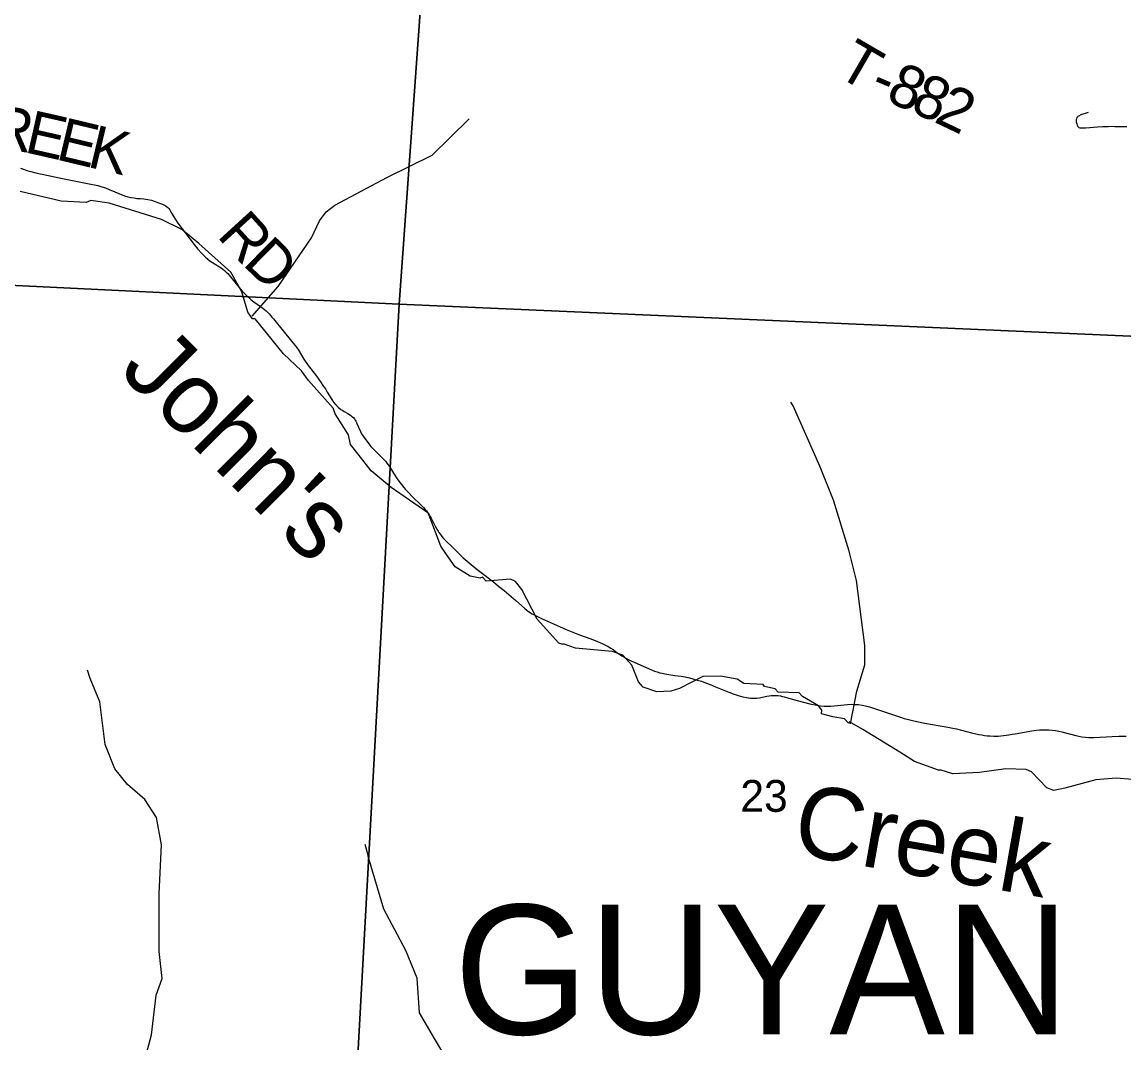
# Model space of a CAD drawing. Extents: x 396.2 to 468.4, y 232.6 to 279.1.
# Drawn here: x 416.745 to 418.195, y 268.432 to 269.775 of the extents above; entities that cross this region are included whole.
import ezdxf

# ---------------------------------------------------------------- set-up
doc = ezdxf.new("R2010")
doc.units = 0
for name, color, linetype in [('GM_X_County_Road', 7, 'Continuous'), ('GM_X_County_Road_Text', 7, 'Continuous'), ('GM_X_Minor_River', 7, 'Continuous'), ('GM_X_Minor_River_Text', 7, 'Continuous'), ('GM_X_Section', 7, 'Continuous'), ('GM_X_Section_Text', 7, 'Continuous'), ('GM_X_Township_Road', 7, 'Continuous'), ('GM_X_Township_Road_Text', 7, 'Continuous'), ('GM_X_Township_Text', 7, 'Continuous')]:
    doc.layers.add(name, color=color, linetype=linetype)

msp = doc.modelspace()

# ---------------------------------------------------------------- linework, layer by layer
at = {"layer": 'GM_X_County_Road'}
for points in [[(416.7431, 269.5829), (416.7469, 269.5815), (416.7512, 269.5799), (416.7568, 269.5783), (416.7633, 269.5767), (416.7981, 269.5693), (416.8356, 269.562), (416.8404, 269.561), (416.845, 269.56), (416.8502, 269.5585), (416.8549, 269.5569), (416.8596, 269.555), (416.8798, 269.5467), (416.8844, 269.5452), (416.8883, 269.5443), (416.8924, 269.5437), (416.8963, 269.5432), (416.9009, 269.5428), (416.9055, 269.5424), (416.9105, 269.5417), (416.9156, 269.5406), (416.9204, 269.5392), (416.9248, 269.5375), (416.9297, 269.5354), (416.9332, 269.5337), (416.935, 269.5326), (416.9367, 269.5313), (416.9382, 269.5297), (416.9395, 269.528), (416.9406, 269.5262), (416.9419, 269.5239), (416.95, 269.5107), (416.9714, 269.4824), (416.9763, 269.4765), (416.9811, 269.4711), (416.9865, 269.4659), (416.9924, 269.461), (416.999, 269.4566), (417.0049, 269.453), (417.0071, 269.4517), (417.0095, 269.4499), (417.0117, 269.4481), (417.0139, 269.4461), (417.016, 269.4441), (417.0178, 269.442), (417.0307, 269.4259), (417.0325, 269.4236), (417.0346, 269.4212), (417.0369, 269.4188), (417.0408, 269.4151), (417.0461, 269.4103), (417.0501, 269.4069), (417.0618, 269.3985), (417.0641, 269.397), (417.0664, 269.3952), (417.0684, 269.3932), (417.0702, 269.3913), (417.0723, 269.3888), (417.0739, 269.3869), (417.0759, 269.3845), (417.0887, 269.3688), (417.0997, 269.3554), (417.1061, 269.3474), (417.1072, 269.3459), (417.1084, 269.3442), (417.116, 269.3315), (417.1218, 269.3233), (417.1316, 269.3105), (417.1378, 269.302), (417.142, 269.2958), (417.1443, 269.2924), (417.1468, 269.2884), (417.1527, 269.2784), (417.1551, 269.2749), (417.1579, 269.2716), (417.1609, 269.2686), (417.1648, 269.2656), (417.1673, 269.264)], [(417.1673, 269.264), (417.169, 269.2629), (417.1738, 269.2602), (417.1773, 269.2579), (417.1787, 269.2568), (417.18, 269.2557), (417.1815, 269.2543), (417.1826, 269.2529), (417.1836, 269.2514), (417.1844, 269.2499), (417.1851, 269.2484), (417.1857, 269.2468), (417.1903, 269.2363), (417.192, 269.2335), (417.1939, 269.2303), (417.2016, 269.22), (417.2042, 269.2169), (417.2074, 269.2133), (417.2144, 269.2063), (417.2165, 269.2043), (417.2183, 269.2025), (417.2203, 269.2005), (417.2222, 269.1986), (417.2237, 269.1968), (417.2253, 269.1948), (417.2269, 269.1927), (417.2285, 269.1905), (417.2341, 269.1817), (417.2398, 269.173), (417.2477, 269.1628), (417.2498, 269.1603), (417.2525, 269.1573), (417.2592, 269.1502), (417.2695, 269.1406), (417.2717, 269.1384), (417.2735, 269.1364), (417.2755, 269.134), (417.2772, 269.1321), (417.2786, 269.13), (417.2799, 269.1281), (417.2811, 269.1264), (417.2822, 269.1246), (417.2833, 269.1225), (417.2844, 269.1206), (417.2888, 269.1119), (417.2909, 269.1081), (417.2925, 269.1054), (417.2937, 269.1036), (417.2956, 269.1009), (417.2976, 269.0984), (417.2998, 269.0958), (417.3034, 269.0922), (417.3116, 269.0843), (417.3258, 269.0704), (417.344, 269.055), (417.3565, 269.0457), (417.3609, 269.0423), (417.3656, 269.0386), (417.3723, 269.0331), (417.3794, 269.0271), (417.395, 269.014), (417.4061, 269.0039), (417.4098, 269.0008), (417.413, 268.9986), (417.4164, 268.9965), (417.4206, 268.9942), (417.4289, 268.9904), (417.4443, 268.9835), (417.4612, 268.9761), (417.4785, 268.969), (417.4921, 268.9639), (417.4993, 268.9613), (417.5054, 268.9589), (417.5092, 268.9573), (417.5127, 268.9555), (417.5164, 268.9535), (417.5198, 268.9515), (417.5229, 268.9495), (417.5259, 268.9472), (417.5304, 268.9439), (417.5345, 268.9411), (417.5383, 268.939), (417.5427, 268.9366), (417.5516, 268.9324), (417.5735, 268.9229), (417.5774, 268.9213), (417.5811, 268.9201), (417.5843, 268.9191), (417.5875, 268.9183), (417.5911, 268.9176), (417.6042, 268.9156), (417.6086, 268.9151), (417.6124, 268.9144), (417.6177, 268.9135), (417.6235, 268.9123), (417.6336, 268.9093), (417.6391, 268.9078), (417.6447, 268.906), (417.6507, 268.9036), (417.6579, 268.9006), (417.6687, 268.896), (417.6751, 268.8933), (417.6808, 268.8912), (417.6873, 268.8891), (417.6936, 268.8873), (417.6986, 268.8863), (417.7036, 268.8857), (417.7082, 268.8854), (417.7123, 268.8856), (417.7158, 268.8861), (417.723, 268.8877), (417.7254, 268.8882), (417.7282, 268.8887), (417.7311, 268.889), (417.7339, 268.8891), (417.7368, 268.8891), (417.74, 268.889), (417.7432, 268.8886), (417.746, 268.888), (417.7482, 268.8874), (417.7653, 268.8825), (417.7819, 268.8782), (417.791, 268.8764), (417.7958, 268.8756), (417.8005, 268.8751), (417.8053, 268.8749), (417.8094, 268.875), (417.8316, 268.8774), (417.8361, 268.8775), (417.841, 268.8774), (417.8458, 268.8771), (417.8505, 268.8764), (417.8553, 268.8754), (417.8603, 268.874), (417.8657, 268.8723), (417.9012, 268.8605), (417.906, 268.859), (417.9117, 268.8574), (417.9171, 268.8561), (417.9226, 268.8549), (417.9332, 268.8528), (417.9636, 268.8474), (417.97, 268.8463), (417.9747, 268.8452), (417.9945, 268.8401), (418.0043, 268.8379), (418.0082, 268.8372), (418.0117, 268.8367), (418.0151, 268.8362), (418.019, 268.8359), (418.024, 268.8356), (418.0297, 268.8358), (418.0333, 268.8361), (418.0367, 268.8364), (418.0402, 268.8368), (418.0439, 268.8374), (418.048, 268.8381), (418.0519, 268.8388), (418.0739, 268.8427), (418.0795, 268.8435), (418.084, 268.8439), (418.0884, 268.844), (418.0927, 268.844), (418.0962, 268.8439), (418.1007, 268.8436), (418.1051, 268.843), (418.1094, 268.8423), (418.1134, 268.8415), (418.132, 268.8366), (418.136, 268.8357), (418.1399, 268.8349), (418.1446, 268.8343), (418.1489, 268.8339), (418.152, 268.8337), (418.1557, 268.8338), (418.1796, 268.8352), (418.1885, 268.8354), (418.1932, 268.8355), (418.198, 268.8354)]]:
    msp.add_lwpolyline(points, dxfattribs=at)
at = {"layer": 'GM_X_Minor_River'}
for points in [[(417.0478, 269.388), (417.082, 269.4272), (417.126, 269.4912), (417.1365, 269.5136), (417.1451, 269.5255), (417.1565, 269.5342), (417.2261, 269.5711), (417.2847, 269.5999), (417.3334, 269.648)], [(417.0891, 269.3388), (417.052, 269.3847), (417.0483, 269.3847), (417.0422, 269.3934), (417.0342, 269.42), (417.0214, 269.4428), (417.0199, 269.4462), (416.9775, 269.4837), (416.9555, 269.5023), (416.9287, 269.5155), (416.8599, 269.537), (416.8357, 269.5404), (416.8293, 269.5377), (416.7964, 269.5395), (416.7427, 269.552)], [(418.2063, 268.7788), (418.1851, 268.7803), (418.1583, 268.7783), (418.1175, 268.7672), (418.1031, 268.7641), (418.0937, 268.7675), (418.0736, 268.7887), (418.0664, 268.7918), (418.0396, 268.7928), (418.0052, 268.7878), (417.97, 268.7862), (417.9549, 268.7911), (417.9511, 268.7911), (417.9194, 268.8024), (417.9005, 268.8145), (417.8517, 268.8444), (417.8339, 268.8546), (417.8328, 268.8527), (417.8275, 268.8584), (417.812, 268.861), (417.7972, 268.8652), (417.7976, 268.8698), (417.7934, 268.8754), (417.7722, 268.8879), (417.7677, 268.8925), (417.7401, 268.8935), (417.7363, 268.8981), (417.7223, 268.9011), (417.7204, 268.9034), (417.6951, 268.9048), (417.6864, 268.9105), (417.6641, 268.9146), (417.6411, 268.9142), (417.6101, 268.8985), (417.5987, 268.8947), (417.5806, 268.8939), (417.5624, 268.8999), (417.5564, 268.9071), (417.5477, 268.9291), (417.5359, 268.942), (417.5219, 268.9469), (417.4736, 268.9514), (417.4584, 268.9567), (417.4554, 268.9567), (417.4513, 268.9578), (417.4232, 268.9896), (417.4028, 269.0287), (417.3945, 269.039), (417.388, 269.042), (417.3559, 269.0396), (417.351, 269.0446), (417.348, 269.0434), (417.3347, 269.046), (417.3151, 269.0585), (417.3037, 269.0745), (417.2961, 269.0855), (417.281, 269.1261), (417.2791, 269.1295), (417.2307, 269.1628), (417.2046, 269.1848), (417.1875, 269.2068), (417.1773, 269.2193), (417.1747, 269.2319), (417.1573, 269.2596), (417.1546, 269.2672), (417.1221, 269.3036), (417.113, 269.3161), (417.0891, 269.3388)], [(417.8355, 268.8517), (417.8436, 268.8948), (417.8541, 268.9294), (417.8541, 268.9548), (417.8431, 269.0406), (417.8337, 269.0789), (417.813, 269.146), (417.7951, 269.191), (417.7597, 269.2703), (417.7568, 269.2749)], [(416.9266, 268.2329), (416.9114, 268.2697), (416.912, 268.313), (416.9195, 268.3495), (416.9187, 268.3731), (416.9079, 268.4016), (416.907, 268.4115), (416.9152, 268.4427), (416.9217, 268.4949), (416.9295, 268.5167), (416.9257, 268.5521), (416.9253, 268.6281), (416.9284, 268.6925), (416.9219, 268.7284), (416.9068, 268.7521), (416.884, 268.7722), (416.8672, 268.7928), (416.8563, 268.8201), (416.8546, 268.8247), (416.8476, 268.8808), (416.8345, 268.9116), (416.8314, 268.9223)], [(417.3363, 268.1294), (417.3359, 268.145), (417.3408, 268.1946), (417.3354, 268.227), (417.3132, 268.3063), (417.3124, 268.3177), (417.317, 268.3328), (417.321, 268.3501), (417.3143, 268.3936), (417.2877, 268.4377), (417.268, 268.4718), (417.2652, 268.5174), (417.25, 268.5536), (417.2211, 268.6081), (417.2012, 268.6759), (417.1999, 268.682), (417.1964, 268.6931)]]:
    msp.add_lwpolyline(points, dxfattribs=at)
at = {"layer": 'GM_X_Section'}
for points in [[(416.2648, 270.4883), (417.3152, 270.4295), (417.2412, 269.4041), (416.2139, 269.4538)], [(417.3152, 270.4295), (418.3421, 270.3767), (418.2741, 269.3589), (417.2412, 269.4041)], [(416.2139, 269.4538), (417.2412, 269.4041), (417.185, 268.384), (416.1543, 268.4231)], [(417.2412, 269.4041), (418.2741, 269.3589), (418.2149, 268.335), (417.185, 268.384)]]:
    msp.add_lwpolyline(points, close=True, dxfattribs=at)
at = {"layer": 'GM_X_Township_Road'}
msp.add_lwpolyline([(418.148, 269.6562), (418.1441, 269.655), (418.1392, 269.6533), (418.1344, 269.6507), (418.1331, 269.6496), (418.1326, 269.648), (418.1323, 269.6465), (418.1325, 269.6439), (418.1331, 269.641), (418.1337, 269.6393), (418.1347, 269.6375), (418.1357, 269.6365), (418.137, 269.636), (418.1398, 269.6358), (418.1449, 269.6361), (418.1605, 269.6372), (418.1671, 269.6376), (418.1745, 269.6379), (418.1791, 269.638), (418.1833, 269.6379), (418.1924, 269.6377), (418.1989, 269.6377)], dxfattribs=at)

# ---------------------------------------------------------------- texts
at = {"layer": 'GM_X_County_Road_Text'}
for s, rotation, p in [('R', 352.3609, (416.7018, 269.6101)), ('E', 347.2922, (416.7468, 269.6042)), ('E', 346.5843, (416.7881, 269.5948)), ('K', 346.5848, (416.8294, 269.585)), ('R', 312.3317, (417.0003, 269.4935)), ('D', 315.5227, (417.0341, 269.4566))]:
    msp.add_text(s, height=0.0568, rotation=rotation, dxfattribs=at).set_placement(p)
at = {"layer": 'GM_X_Minor_River_Text'}
for s, rotation, p in [("John's", 315.0035, (416.871, 269.315)), ('Creek', 350.0126, (417.7562, 268.6816))]:
    msp.add_text(s, height=0.09469, rotation=rotation, dxfattribs=at).set_placement(p)
at = {"layer": 'GM_X_Section_Text'}
msp.add_text('23', height=0.04186, rotation=0, dxfattribs=at).set_placement((417.6904, 268.7361))
at = {"layer": 'GM_X_Township_Road_Text'}
for s, rotation, p in [('T', 329.8543, (417.8148, 269.7059)), ('8', 336.7416, (417.8799, 269.672)), ('-', 337.0685, (417.8585, 269.6811)), ('8', 336.3405, (417.912, 269.6582)), ('2', 334.5195, (417.9436, 269.6444))]:
    msp.add_text(s, height=0.0568, rotation=rotation, dxfattribs=at).set_placement(p)
at = {"layer": 'GM_X_Township_Text'}
msp.add_text('GUYAN', height=0.17045, rotation=0, dxfattribs=at).set_placement((417.3136, 268.4433))

doc.saveas('drawing.dxf')
